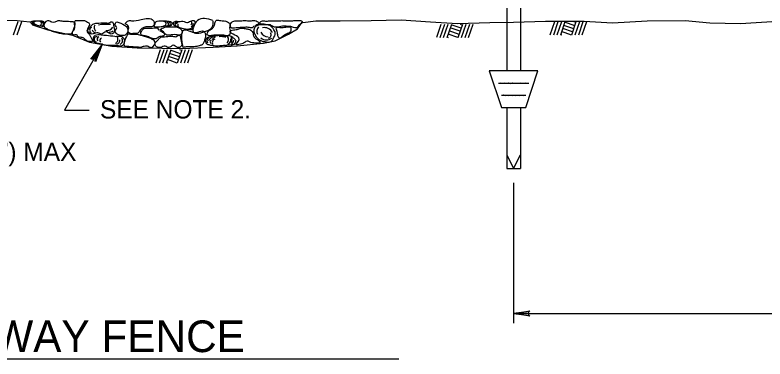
# Model space of a CAD drawing. Extents: x 13 to 918, y -903 to 879.
# Drawn here: x 317.7 to 445.7, y 669.1 to 727.8 of the extents above; entities that cross this region are included whole.
import ezdxf

# ---------------------------------------------------------------- set-up
doc = ezdxf.new("R2010")
doc.units = 0
for name, color, linetype in [('1', 7, 'Continuous'), ('2', 7, 'Continuous'), ('3', 7, 'Continuous')]:
    doc.layers.add(name, color=color, linetype=linetype)

msp = doc.modelspace()

# ---------------------------------------------------------------- linework, layer by layer
at = {"layer": '1'}
for p, q in [((318.173, 726.58275), (317.38975, 724.314)), ((318.771, 726.58275), (317.9855, 724.314)), ((390.36875, 726.14325), (389.596, 723.91625)), ((390.96475, 726.14325), (390.17725, 723.8745)), ((391.5605, 726.14325), (390.773, 723.8745)), ((392.15625, 726.14325), (391.36875, 723.8745)), ((393.8335, 725.5015), (392.1375, 726.089)), ((394.0375, 726.14325), (393.25225, 723.8745)), ((394.01675, 726.03275), (393.70225, 726.14325)), ((394.6335, 726.14325), (393.848, 723.8745)), ((395.22725, 726.14325), (394.44375, 723.8745)), ((395.825, 726.14325), (395.03975, 723.8745)), ((409.7605, 726.564), (408.9875, 724.337)), ((410.35625, 726.564), (409.56875, 724.29525)), ((410.95225, 726.564), (410.16475, 724.29525)), ((411.548, 726.564), (410.7605, 724.29525)), ((413.04175, 725.39125), (411.346, 725.98075)), ((413.225, 725.9225), (411.52925, 726.51)), ((413.42925, 726.564), (412.64375, 724.29525)), ((413.4085, 726.45375), (413.09375, 726.564)), ((414.025, 726.564), (413.23975, 724.29525)), ((414.61875, 726.564), (413.8355, 724.29525)), ((415.21675, 726.564), (414.43125, 724.29525)), ((393.46675, 724.439), (391.76875, 725.0245)), ((393.65, 724.97025), (391.95425, 725.56)), ((412.673, 724.32875), (410.975, 724.914)), ((412.8585, 724.86), (411.1605, 725.44525)), ((391.648, 723.8745), (391.4, 723.962)), ((393.28125, 723.90775), (391.5835, 724.49325)), ((411.03975, 724.29525), (410.79175, 724.38275)), ((342.471, 721.787), (341.698, 719.56)), ((343.06675, 721.787), (342.27925, 719.51825)), ((343.6625, 721.787), (342.875, 719.51825)), ((344.2585, 721.787), (343.471, 719.51825)), ((345.75225, 720.614), (344.05625, 721.20375)), ((345.9355, 721.14525), (344.23975, 721.73275)), ((346.13975, 721.787), (345.35425, 719.51825)), ((346.11875, 721.6765), (345.80425, 721.787)), ((346.7355, 721.787), (345.95, 719.51825)), ((347.32925, 721.787), (346.546, 719.51825)), ((347.92725, 721.787), (347.14175, 719.51825)), ((343.75, 719.51825), (343.50225, 719.60575)), ((345.3835, 719.5515), (343.6855, 720.137)), ((345.56875, 720.08275), (343.871, 720.66825))]:
    msp.add_line(p, q, dxfattribs=at)
at = {"layer": '2'}
for p, q in [((401.598, 818.15575), (401.598, 718.185)), ((403.948, 818.15575), (403.948, 718.2265)), ((402.773, 726.54525), (402.773, 726.54525)), ((402.773, 726.54525), (402.773, 726.54525)), ((402.773, 726.54525), (402.773, 726.54525)), ((402.773, 726.54525), (402.773, 726.54525)), ((332.5085, 722.58075), (326.1105, 711.4975)), ((406.93975, 718.2225), (398.60625, 718.2225)), ((398.60625, 718.2225), (400.68975, 711.9725)), ((404.85625, 711.9725), (406.93975, 718.2225)), ((400.19175, 716.139), (405.3875, 716.139)), ((400.68975, 714.05575), (404.85625, 714.05575)), ((400.68975, 711.9725), (404.85625, 711.9725)), ((401.598, 711.987), (401.598, 701.55575)), ((403.948, 711.96625), (403.948, 701.55575)), ((326.1105, 711.4975), (330.3625, 711.4975)), ((401.598, 703.90575), (402.773, 701.55575)), ((402.773, 701.55575), (403.948, 703.90575)), ((401.598, 701.55575), (403.948, 701.55575)), ((402.773, 699.14125), (402.773, 675.18275)), ((402.773, 676.85775), (552.773, 676.85775))]:
    msp.add_line(p, q, dxfattribs=at)
for points in [[(314.88125, 726.85775), (318.06475, 726.8015), (320.19375, 726.60775), (320.3335, 726.59325)], [(320.323, 726.5515), (320.6875, 726.09325), (323.298, 725.2245), (327.5105, 724.29125), (330.3835, 723.1475), (334.2, 722.414), (338.5355, 722.15375), (342.75, 722.07875), (346.23125, 722.01625), (351.498, 722.29125), (355.58975, 722.49125), (360.07925, 722.9495), (362.1105, 723.34525), (364.3855, 724.4745), (365.88125, 725.39125), (366.68975, 726.5515)], [(366.81875, 726.49525), (369.05, 726.74325), (373.173, 726.74325), (378.4875, 726.82025), (383.571, 726.91625), (388.61475, 726.57025), (393.18125, 726.28275), (398.70425, 726.4745), (402.773, 726.54525), (408.2, 726.685), (414.8355, 726.7245), (419.65, 726.3975), (425.5585, 726.78075), (432.0625, 726.82025), (436.24375, 726.3975), (441.47925, 726.3015), (447.771, 726.7245)], [(400.19175, 716.139), (400.49175, 716.17875), (400.9335, 716.0995), (401.25425, 716.16), (401.61475, 716.0995), (401.9355, 716.16), (402.298, 716.07875), (402.61875, 716.16), (402.9605, 716.0995), (403.2605, 716.139), (403.6625, 716.0995), (404.023, 716.16), (404.425, 716.11825), (404.746, 716.17875), (405.06675, 716.11825), (405.3875, 716.139)], [(400.68975, 714.05575), (400.973, 714.13275), (401.3335, 714.03275), (401.61475, 714.09325), (401.91675, 714.012), (402.21675, 714.0725), (402.57925, 714.012), (402.83975, 714.09325), (403.17925, 714.012), (403.50225, 714.09325), (403.8625, 714.012), (404.20425, 714.0725), (404.4835, 714.03275), (404.85625, 714.05575)]]:
    msp.add_lwpolyline(points, dxfattribs=at)
for centre, radius, start, end in [((320.87486, 726.44785), 0.20386, 73.9008972, 260.0747056), ((321.1032, 726.43285), 0.20386, 73.9008972, 260.0747056), ((321.88661, 726.32796), 0.34499, 289.1403778, 73.4767417), ((322.17661, 726.2363), 0.34499, 289.1403778, 73.4767417), ((331.90224, 725.60346), 0.72723, 143.8898139, 234.6405278), ((333.18906, 719.94859), 6.21345, 82.4878139, 101.740775), ((343.06389, 726.26957), 0.38924, 270.8593028, 91.3488278), ((343.47889, 726.23305), 0.39486, 308.8135889, 73.6992806), ((343.9512, 726.22885), 0.26953, 287.6795083, 76.0038417), ((345.25511, 726.24499), 0.2938, 96.2627722, 248.2823278), ((345.69867, 726.06395), 0.51999, 85.1032667, 166.4959306), ((345.70798, 726.06371), 0.25688, 129.4594167, 230.5405833), ((347.31015, 726.27579), 0.88396, 271.2691472, 332.3359056), ((347.39706, 726.39514), 0.46841, 314.9620333, 25.5331167), ((347.15254, 726.57241), 1.02268, 304.2466194, 348.5107278), ((330.8817, 725.15806), 0.47137, 108.3811, 243.728525), ((331.51321, 725.40611), 0.67149, 197.0962889, 267.2839111), ((333.30203, 726.33764), 1.25579, 265.7086444, 326.8194083), ((333.92776, 725.63147), 0.78413, 251.6877889, 312.7194806), ((360.16323, 724.92416), 1.21393, 139.5311611, 202.4609083), ((360.89376, 725.37479), 1.35776, 203.7922389, 269.7592417), ((360.28442, 724.13476), 1.46468, 25.5022056, 103.5443917), ((360.77491, 724.39072), 0.61249, 286.5838389, 30.7309361), ((331.62324, 723.61018), 0.4405, 82.6327472, 259.5121944), ((332.13897, 723.62288), 0.44433, 112.3900083, 220.8863333), ((332.59731, 723.40788), 0.44433, 112.3900083, 220.8863333), ((334.51401, 723.58288), 0.73393, 297.8072778, 30.4995444), ((334.85567, 723.43777), 0.71034, 288.8119806, 8.57735), ((335.29235, 723.42955), 0.73393, 297.8072778, 30.4995444), ((350.93627, 723.35314), 0.50457, 100.8380417, 227.9100361), ((352.04182, 722.6655), 1.45949, 116.4651139, 154.939125), ((351.23732, 723.17038), 0.26239, 106.4393583, 253.5606389), ((352.25009, 722.98535), 1.06698, 107.6605361, 151.2405889), ((352.04349, 722.9973), 0.69535, 110.0828556, 203.6189639), ((352.93334, 722.28543), 1.77652, 66.1596361, 102.9112028), ((353.23609, 723.59944), 0.88599, 318.1828722, 33.9086333), ((353.73094, 723.49992), 0.77824, 289.2918056, 12.2751778), ((354.11646, 723.44313), 0.6183, 321.1612806, 49.0865806), ((353.77231, 723.82876), 1.32816, 306.8078889, 342.8462861), ((360.6026, 725.06681), 1.55477, 231.5782417, 306.6062)]:
    msp.add_arc(centre, radius, start, end, dxfattribs=at)
for points in [[(337.971, 724.612), (337.2085, 724.65775), (336.99375, 724.93275), (337.0855, 725.54325), (336.948, 725.987), (336.55225, 726.262), (336.90225, 726.70375), (337.575, 726.78075), (339.2085, 726.964), (341.2855, 726.8265), (341.45225, 726.29125), (341.146, 725.81825), (340.44375, 725.7265), (339.65, 725.635), (339.2085, 725.33075), (338.9335, 724.97875), (338.5355, 724.612), (338.01675, 724.612)], [(351.45225, 726.81), (348.8105, 726.81), (348.09375, 724.8725), (350.398, 725.04125), (351.3605, 725.712), (351.498, 726.76625)], [(322.48975, 725.7745), (322.1375, 725.83275), (321.725, 725.89525), (321.2835, 726.0495), (320.77925, 726.139), (320.4585, 726.36825), (320.4585, 726.58275), (320.596, 726.70375), (321.06875, 726.7495), (321.573, 726.7495), (322.046, 726.735), (322.4125, 726.70375), (322.6105, 726.49125), (322.64175, 726.1995), (322.55, 725.83275), (322.51875, 725.7745)], [(327.3, 724.56625), (327.74175, 726.5515), (327.11675, 726.5995), (326.55225, 726.64325), (325.7105, 726.69125), (324.99375, 726.735), (324.475, 726.5515), (323.9855, 726.50775), (323.6355, 726.69125), (323.2375, 726.78275), (322.6585, 725.75775), (322.9625, 725.4995), (323.496, 725.2245), (324.2, 724.96625), (325.03975, 724.735), (325.8335, 724.56625), (326.55225, 724.56625), (327.3, 724.5225)], [(329.9105, 724.97875), (330.321, 724.4745), (330.58125, 724.09325), (330.76475, 723.62025), (330.825, 723.239), (330.55225, 723.20775), (329.925, 723.3745), (329.54375, 723.68275), (329.0085, 723.94125), (328.50425, 724.0015), (328.1855, 724.35375), (327.65, 724.35375), (327.496, 724.8265), (327.8335, 725.33075), (327.89375, 725.80375), (327.8335, 726.139), (327.8625, 726.64325), (328.03125, 726.812), (328.44375, 726.812), (329.03975, 726.84125), (329.66475, 726.7495), (330.046, 726.5515), (330.3835, 726.1995), (330.29175, 725.83275), (330.07725, 725.39125), (329.925, 724.97875)], [(333.65, 726.3515), (332.8855, 726.44325), (331.696, 726.3515), (330.948, 726.185), (330.596, 725.787), (330.2, 725.3745), (330.1085, 724.9495), (330.36875, 724.6265), (331.03975, 724.535), (331.8335, 724.71825), (332.44375, 724.50575), (333.2085, 724.9015), (333.9105, 724.535), (334.2605, 724.535), (334.6105, 724.85775), (334.6105, 725.4225), (334.48975, 726.0015), (334.30625, 726.58275), (333.65, 726.3515)], [(335.05225, 726.614), (336.38125, 726.03275), (336.90225, 725.46825), (336.596, 724.3995), (335.9855, 724.23275), (335.3605, 724.35575), (334.77725, 725.0725), (335.05225, 725.54525), (334.77725, 726.08075), (335.0085, 726.614)], [(343.17725, 725.81825), (342.6125, 725.7265), (342.07725, 725.68275), (341.45225, 725.81825), (341.58975, 726.262), (341.72725, 726.612), (342.21475, 726.735), (342.871, 726.78075), (343.52725, 726.735), (343.971, 726.70375), (344.36875, 726.5225), (344.4605, 726.21625), (344.323, 725.987), (343.971, 725.86625), (343.31475, 725.81825)], [(348.16875, 725.635), (347.9105, 725.28275), (347.25425, 725.28275), (346.62725, 725.33075), (345.8355, 725.59125), (345.34375, 725.7745), (344.85625, 725.987), (344.7355, 726.4745), (344.99375, 726.65775), (345.60425, 726.65775), (346.5355, 726.65775), (346.97925, 726.4745), (347.60425, 726.70375), (348.3085, 726.735), (348.4, 726.43075), (348.2605, 725.94125), (348.16875, 725.68275)], [(353.4835, 726.735), (354.09375, 726.4745), (354.36875, 726.07875), (354.27725, 725.59125), (354.4, 725.1015), (354.36875, 724.537), (354.13975, 724.262), (353.346, 724.30775), (352.55225, 724.30775), (351.80425, 724.30775), (350.96475, 724.21625), (350.47725, 724.35375), (350.56875, 724.84125), (350.96475, 725.239), (351.3605, 725.4515), (351.66675, 725.89525), (351.85, 726.5225), (351.971, 726.78075), (352.598, 726.8265), (353.4375, 726.735)], [(358.521, 725.89525), (358.171, 725.59125), (357.5, 725.635), (356.70425, 725.635), (355.423, 725.54325), (354.5355, 725.635), (354.44375, 726.07875), (354.62725, 726.4745), (354.84375, 726.65775), (355.60625, 726.735), (356.4, 726.78075), (357.3605, 726.78075), (358.0335, 726.78075), (358.82725, 726.735), (359.26875, 726.339), (358.96475, 726.07875), (358.64375, 725.89525)], [(359.973, 723.25575), (359.1335, 723.74325), (358.64375, 724.3995), (358.43125, 725.0245), (358.64375, 725.68275), (359.0875, 725.987), (360.325, 726.07875), (361.16475, 725.94125), (361.74375, 725.4225), (362.096, 724.70575), (361.74375, 723.6975), (361.425, 723.25575), (360.62925, 723.164), (359.973, 723.25575)], [(363.57725, 725.86625), (363.071, 725.7745), (362.56875, 725.68275), (362.15625, 725.68275), (361.8355, 725.712), (361.52925, 725.89525), (361.26875, 726.0495), (360.8585, 726.0495), (360.323, 726.15575), (359.7585, 726.21625), (359.4855, 726.36825), (359.72725, 726.72025), (360.42925, 726.72025), (361.0855, 726.7495), (362.0335, 726.7495), (362.8875, 726.78075), (363.57725, 726.78075), (364.20225, 726.7495), (364.70625, 726.7495), (365.4375, 726.812), (366.15625, 726.812), (366.6, 726.7495), (366.68975, 726.5515), (366.27725, 726.10775), (366.12725, 726.01625), (365.9105, 725.68275), (365.621, 725.54325), (365.2105, 725.62025), (364.90425, 725.74125), (364.29375, 725.80375), (363.6355, 725.86625)], [(342.3375, 725.1015), (342.77925, 724.84125), (343.223, 724.3995), (343.0105, 724.21625), (342.246, 724.0015), (341.94175, 723.7745), (341.146, 723.74125), (340.48975, 724.0015), (339.696, 724.21625), (339.2085, 724.3995), (339.37725, 725.1475), (339.72725, 725.4515), (340.44375, 725.4995), (341.37725, 725.54325), (341.9855, 725.4995), (342.246, 725.1475)], [(342.4375, 725.2975), (343.2125, 725.66), (344.4335, 725.73275), (345.17725, 725.70775), (346.21875, 724.9495), (345.86875, 724.34125), (345.371, 724.362), (344.34375, 724.35775), (343.57725, 724.34125), (343.1355, 724.737), (342.55625, 725.22875)], [(346.36875, 722.1995), (346.23125, 723.04125), (346.13975, 724.0475), (346.4, 725.11625), (348.6125, 724.7495), (349.68125, 725.0245), (349.9855, 724.887), (350.16875, 724.3995), (350.16875, 723.95575), (349.94175, 723.25375), (349.72725, 722.76625), (349.2855, 722.5515), (348.49175, 722.36825), (347.95625, 722.3225), (347.071, 722.3225), (346.323, 722.23075)], [(355.346, 722.6745), (355.86475, 723.86625), (354.41475, 724.98075), (354.76675, 725.19325), (355.60625, 725.285), (356.1855, 725.514), (356.97925, 725.4225), (357.58975, 725.33075), (358.171, 724.93275), (358.3085, 724.537), (358.521, 723.95775), (358.91875, 723.60575), (359.31675, 723.3475), (359.5, 723.0725), (358.42925, 722.99525), (357.9105, 723.0725), (357.5, 723.2995), (357.071, 723.20775), (356.5835, 722.90375), (356.13975, 722.76625), (355.60625, 722.6745), (355.423, 722.6745)], [(364.36875, 724.62875), (363.696, 724.3245), (362.7355, 723.83275), (362.55225, 724.185), (362.41475, 724.93275), (362.29375, 725.514), (363.17725, 725.635), (364.1855, 725.7265), (364.71875, 725.68275), (364.76675, 725.33075), (364.675, 724.93275), (364.41475, 724.6745)], [(334.7355, 724.09325), (333.2835, 724.23075), (332.398, 724.3225), (331.32925, 724.23075), (331.025, 723.83275), (331.025, 723.437), (331.46675, 723.04125), (332.35225, 722.85775), (333.1, 722.64325), (334.03125, 722.5975), (334.871, 722.5975), (335.45225, 722.50575), (335.80225, 722.50575), (336.29175, 722.81), (336.4125, 723.20775), (336.246, 723.74125), (335.89375, 724.0015), (335.17725, 724.09325), (334.77925, 724.0475)], [(336.90225, 724.44525), (336.4605, 722.46), (337.0855, 722.414), (337.65, 722.36825), (338.48975, 722.3225), (339.2085, 722.2765), (339.72725, 722.46), (340.21475, 722.50575), (340.56675, 722.3225), (340.9625, 722.23075), (341.54375, 723.25375), (341.2375, 723.514), (340.70425, 723.789), (340.00225, 724.0475), (339.1605, 724.2765), (338.36875, 724.44525), (337.65, 724.44525), (336.90225, 724.49125)], [(345.13125, 724.0475), (344.36875, 724.139), (343.17725, 724.0475), (342.42925, 723.88075), (342.07725, 723.48275), (341.68125, 723.07025), (341.58975, 722.64325), (341.85, 722.3225), (342.521, 722.23075), (343.31475, 722.414), (343.92725, 722.1995), (344.68975, 722.5975), (345.39175, 722.23075), (345.74375, 722.23075), (346.09375, 722.5515), (346.09375, 723.11625), (345.971, 723.6975), (345.7875, 724.2765), (345.13125, 724.0475)], [(353.46875, 722.56625), (352.62725, 722.4745), (351.65, 722.4745), (350.948, 722.614), (350.4125, 722.8265), (350.246, 723.17875), (350.4125, 723.80375), (350.7355, 724.01625), (351.575, 724.15575), (352.58125, 724.29125), (353.72725, 724.1995), (354.56675, 724.15575), (354.8855, 723.88075), (355.32925, 723.48275), (355.2375, 723.01), (354.70425, 722.614), (354.09375, 722.614), (353.421, 722.4745)]]:
    msp.add_spline(points, degree=3, dxfattribs=at)
at = {"layer": '3'}
msp.add_line((249.04053, 669.08875), (383.21194, 669.08875), dxfattribs=at)
for points in [[(330.78125, 720.3015), (331.0125, 720.289), (332.5085, 722.58075), (330.78125, 720.3015), (330.6, 720.237), (332.5085, 722.58075), (331.2605, 720.1495), (331.3875, 719.96), (332.5085, 722.58075), (331.42725, 719.76), (331.3875, 719.96)], [(405.421, 676.5245), (405.323, 676.71625), (402.773, 676.85775), (405.421, 676.5245), (405.5585, 676.41), (402.773, 676.85775), (405.321, 676.98275), (405.41475, 677.1745), (402.773, 676.85775), (405.5585, 677.2995), (405.41475, 677.1745)]]:
    msp.add_lwpolyline(points, dxfattribs=at)

# ---------------------------------------------------------------- texts
for s, height, p in [('SEE NOTE 2.', 3.1249995, (332.18125, 710.10575)), ('75 (3") MAX', 3.1249995, (305.5395, 702.87325)), ('TYPE 5 RIGHT-OF-WAY FENCE', 5.4020865, (249.753, 670.26175))]:
    msp.add_text(s, height=height, dxfattribs=at).set_placement(p)

doc.saveas('drawing.dxf')
